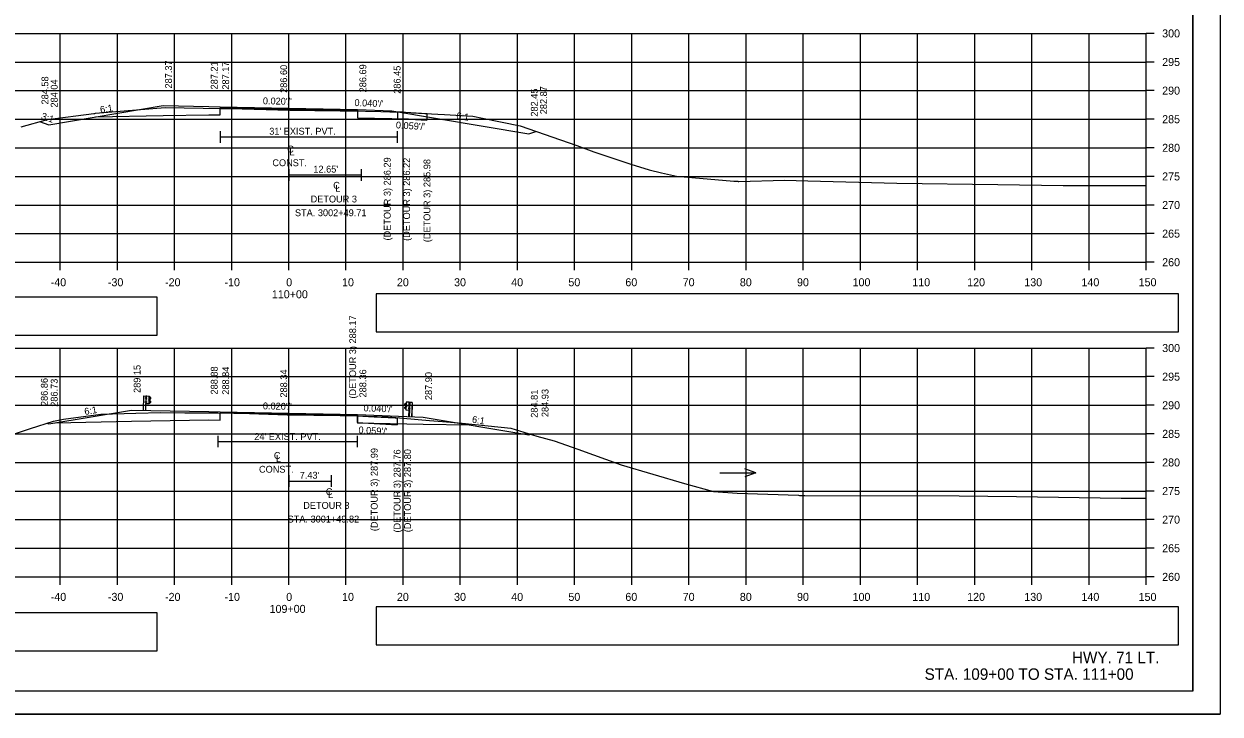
# Model space of a CAD drawing. Extents: x 285 to 4233, y -659 to 3710.
# Drawn here: x 492.9 to 702.2, y 189.5 to 310.1 of the extents above; entities that cross this region are included whole.
import ezdxf

# ---------------------------------------------------------------- set-up
doc = ezdxf.new("R2010")
doc.units = 0
for name, color, linetype in [('R_Alt Surface', 7, 'Continuous'), ('R_Axis', 7, 'Continuous'), ('R_Axis Annot', 7, 'Continuous'), ('R_Border', 7, 'Continuous'), ('R_Detour', 7, 'Continuous'), ('R_Draft', 7, 'Continuous'), ('R_Exist Surface', 7, 'Continuous'), ('R_Fin Surface', 7, 'Continuous'), ('R_Grid', 7, 'Continuous'), ('R_No Plot', 7, 'Continuous'), ('R_Proposed Road', 7, 'Continuous'), ('R_Water', 7, 'Continuous'), ('R_Water Annot', 7, 'Continuous'), ('R_Xsect Elev', 7, 'Continuous'), ('R_Xsect Slope', 7, 'Continuous')]:
    doc.layers.add(name, color=color, linetype=linetype)

# ---------------------------------------------------------------- blocks, each defined once
blk = doc.blocks.new('GUARDRAIL RT_P')
at = {"layer": 'R_Proposed Road'}
for p, q in [((-1.3, 2.2), (-1.17, 2.3)), ((-1.28, 2.18), (-1.16, 2.29)), ((-1.17, 2.3), (-1.06, 2.36)), ((-1.16, 2.29), (-1.06, 2.34)), ((-1.02, 1.15), (-1.02, 2.51)), ((-0.53, 2.21), (-0.58, 2.21)), ((-0.58, 2.21), (-0.58, 2.08)), ((-0.58, 2.15), (-0.52, 2.15)), ((-0.53, 2.52), (-0.52, 2.52)), ((-0.53, 2.52), (-0.46, 2.51)), ((-0.49, 0), (-0.49, 2.52)), ((-0.46, 2.09), (-0.46, 2.21)), ((-0.46, 2.21), (-0.41, 2.21)), ((-0.46, 2.18), (-0.41, 2.18)), ((-0.46, 2.12), (-0.41, 2.12)), ((-0.46, 2.12), (-0.41, 2.12)), ((-0.4, 2.11), (-0.4, 2.2)), ((-0.03, 2.52), (-0.03, 0)), ((0, 2.52), (0, 0)), ((-1.17, 1.35), (-1.3, 1.46)), ((-1.12, 1.95), (-1.29, 2.05)), ((-1.16, 1.37), (-1.29, 1.48)), ((-1.11, 1.97), (-1.28, 2.07)), ((-1.27, 1.62), (-1.12, 1.71)), ((-1.26, 1.6), (-1.1, 1.69)), ((-1.06, 1.29), (-1.17, 1.35)), ((-1.05, 1.31), (-1.16, 1.37)), ((-1.09, 1.77), (-1.09, 1.9)), ((-1.06, 1.77), (-1.06, 1.9)), ((-1.01, 1.77), (-1.01, 1.89)), ((-1.01, 1.89), (-0.96, 1.89)), ((-1.01, 1.86), (-0.96, 1.86)), ((-1.01, 1.8), (-0.97, 1.8)), ((-1.01, 1.8), (-0.96, 1.8)), ((-1.01, 1.77), (-0.96, 1.77)), ((-0.96, 1.78), (-0.96, 1.88)), ((-0.53, 2.08), (-0.58, 2.08)), ((-0.58, 1.4), (-0.58, 1.53)), ((-0.58, 1.53), (-0.53, 1.53)), ((-0.58, 1.46), (-0.52, 1.46)), ((-0.58, 1.4), (-0.53, 1.4)), ((-0.52, 1.15), (-0.49, 1.15)), ((-0.46, 2.09), (-0.41, 2.09)), ((-0.45, 1.4), (-0.45, 1.53)), ((-0.45, 1.53), (-0.4, 1.53)), ((-0.45, 1.49), (-0.4, 1.49)), ((-0.45, 1.43), (-0.4, 1.43)), ((-0.45, 1.43), (-0.4, 1.43)), ((-0.45, 1.4), (-0.4, 1.4)), ((-0.39, 1.42), (-0.39, 1.51))]:
    blk.add_line(p, q, dxfattribs=at)
for points in [[(-1.05, 2.52), (-1.05, 1.15), (-0.52, 1.15), (-0.53, 2.52)], [(-0.58, 2.21), (-0.58, 2.08), (-0.53, 2.08), (-0.53, 2.21)], [(-0.45, 2.23), (-0.45, 2.07), (-0.46, 2.07), (-0.46, 2.23)], [(-0.4, 2.18), (-0.4, 2.12), (-0.37, 2.12), (-0.37, 2.18)], [(-1.01, 1.91), (-1.01, 1.75), (-1.02, 1.75), (-1.02, 1.91)], [(-0.95, 1.86), (-0.95, 1.8), (-0.93, 1.8), (-0.93, 1.86)], [(-0.58, 1.53), (-0.58, 1.4), (-0.53, 1.4), (-0.53, 1.53)], [(-0.44, 1.55), (-0.44, 1.38), (-0.45, 1.38), (-0.45, 1.55)], [(-0.39, 1.49), (-0.39, 1.43), (-0.36, 1.43), (-0.36, 1.49)]]:
    blk.add_lwpolyline(points, close=True, dxfattribs=at)
blk.add_lwpolyline([(0, 2.52), (-0.46, 2.51), (-0.45, 0)], dxfattribs=at)
for centre, radius, start, end in [((-1.25, 2.13), 0.0856, 122.0217, 240.7501), ((-1.25, 2.13), 0.062, 122.0217, 240.7501), ((-0.42, 2.2), 0.022, 317.7756, 45.4255), ((-0.49, 2.15), 0.0922, 339.7423, 20.2577), ((-0.43, 2.1), 0.025, 323.3766, 39.0666), ((-1.22, 1.52), 0.109, 120.88, 214.7816), ((-1.22, 1.52), 0.0854, 120.88, 214.7816), ((-1.08, 1.83), 0.0453, 93.9303, 257.0446), ((-1.15, 1.89), 0.0622, 4.9556, 61.894), ((-1.15, 1.89), 0.0865, 4.9556, 61.894), ((-1.13, 1.76), 0.0462, 293.1464, 8.2196), ((-1.13, 1.76), 0.0703, 293.1464, 8.2196), ((-0.98, 1.88), 0.022, 317.7756, 45.4255), ((-1.05, 1.83), 0.0922, 339.7423, 20.2577), ((-0.98, 1.78), 0.025, 323.3766, 39.0666), ((-0.41, 1.51), 0.022, 317.7756, 45.4255), ((-0.48, 1.46), 0.0922, 339.7423, 20.2577), ((-0.41, 1.41), 0.025, 323.3766, 39.0666)]:
    blk.add_arc(centre, radius, start, end, dxfattribs=at)
blk = doc.blocks.new('GUARDRAIL LT_P')
at = {"layer": 'R_Proposed Road'}
for p, q in [((0, 2.52), (0, 0)), ((0.03, 2.52), (0.03, 0)), ((0.4, 2.11), (0.4, 2.2)), ((0.46, 2.21), (0.41, 2.21)), ((0.46, 2.18), (0.41, 2.18)), ((0.46, 2.12), (0.41, 2.12)), ((0.46, 2.12), (0.41, 2.12)), ((0.53, 2.52), (0.46, 2.51)), ((0.46, 2.09), (0.46, 2.21)), ((0.49, 0), (0.49, 2.52)), ((0.53, 2.52), (0.52, 2.52)), ((0.58, 2.15), (0.52, 2.15)), ((0.53, 2.21), (0.58, 2.21)), ((0.58, 2.21), (0.58, 2.08)), ((1.02, 1.15), (1.02, 2.51)), ((1.17, 2.3), (1.06, 2.36)), ((1.16, 2.29), (1.06, 2.34)), ((1.28, 2.18), (1.16, 2.29)), ((1.3, 2.2), (1.17, 2.3)), ((0.39, 1.42), (0.39, 1.51)), ((0.45, 1.53), (0.4, 1.53)), ((0.45, 1.49), (0.4, 1.49)), ((0.45, 1.43), (0.4, 1.43)), ((0.45, 1.43), (0.4, 1.43)), ((0.45, 1.4), (0.4, 1.4)), ((0.46, 2.09), (0.41, 2.09)), ((0.45, 1.4), (0.45, 1.53)), ((0.52, 1.15), (0.49, 1.15)), ((0.58, 1.46), (0.52, 1.46)), ((0.53, 2.08), (0.58, 2.08)), ((0.58, 1.53), (0.53, 1.53)), ((0.58, 1.4), (0.53, 1.4)), ((0.58, 1.4), (0.58, 1.53)), ((1.01, 1.89), (0.96, 1.89)), ((0.96, 1.78), (0.96, 1.88)), ((1.01, 1.86), (0.96, 1.86)), ((1.01, 1.8), (0.96, 1.8)), ((1.01, 1.77), (0.96, 1.77)), ((1.01, 1.8), (0.97, 1.8)), ((1.01, 1.77), (1.01, 1.89)), ((1.05, 1.31), (1.16, 1.37)), ((1.06, 1.77), (1.06, 1.9)), ((1.06, 1.29), (1.17, 1.35)), ((1.09, 1.77), (1.09, 1.9)), ((1.26, 1.6), (1.1, 1.69)), ((1.11, 1.97), (1.28, 2.07)), ((1.12, 1.95), (1.29, 2.05)), ((1.27, 1.62), (1.12, 1.71)), ((1.16, 1.37), (1.29, 1.48)), ((1.17, 1.35), (1.3, 1.46))]:
    blk.add_line(p, q, dxfattribs=at)
blk.add_lwpolyline([(0, 2.52), (0.46, 2.51), (0.45, 0)], dxfattribs=at)
for points in [[(0.4, 2.18), (0.4, 2.12), (0.37, 2.12), (0.37, 2.18)], [(0.45, 2.23), (0.45, 2.07), (0.46, 2.07), (0.46, 2.23)], [(1.05, 2.52), (1.05, 1.15), (0.52, 1.15), (0.53, 2.52)], [(0.58, 2.21), (0.58, 2.08), (0.53, 2.08), (0.53, 2.21)], [(0.39, 1.49), (0.39, 1.43), (0.36, 1.43), (0.36, 1.49)], [(0.44, 1.55), (0.44, 1.38), (0.45, 1.38), (0.45, 1.55)], [(0.58, 1.53), (0.58, 1.4), (0.53, 1.4), (0.53, 1.53)], [(0.95, 1.86), (0.95, 1.8), (0.93, 1.8), (0.93, 1.86)], [(1.01, 1.91), (1.01, 1.75), (1.02, 1.75), (1.02, 1.91)]]:
    blk.add_lwpolyline(points, close=True, dxfattribs=at)
for centre, radius, start, end in [((0.42, 2.2), 0.022, 134.5745, 222.2244), ((0.49, 2.15), 0.0922, 159.7423, 200.2577), ((0.43, 2.1), 0.025, 140.9334, 216.6234), ((1.25, 2.13), 0.062, 299.2499, 57.9783), ((1.25, 2.13), 0.0856, 299.2499, 57.9783), ((0.41, 1.51), 0.022, 134.5745, 222.2244), ((0.48, 1.46), 0.0922, 159.7423, 200.2577), ((0.41, 1.41), 0.025, 140.9334, 216.6234), ((0.98, 1.88), 0.022, 134.5745, 222.2244), ((1.05, 1.83), 0.0922, 159.7423, 200.2577), ((0.98, 1.78), 0.025, 140.9334, 216.6234), ((1.15, 1.89), 0.0865, 118.106, 175.0444), ((1.13, 1.76), 0.0703, 171.7804, 246.8536), ((1.08, 1.83), 0.0453, 282.9554, 86.0697), ((1.15, 1.89), 0.0622, 118.106, 175.0444), ((1.13, 1.76), 0.0462, 171.7804, 246.8536), ((1.22, 1.52), 0.0854, 325.2184, 59.12), ((1.22, 1.52), 0.109, 325.2184, 59.12)]:
    blk.add_arc(centre, radius, start, end, dxfattribs=at)

msp = doc.modelspace()

# ---------------------------------------------------------------- linework, layer by layer
at = {"layer": 'R_Alt Surface'}
for points in [[(505.44, 293.89), (517.28, 294.12), (525.28, 294.28), (527.28, 294.24), (527.28, 295.49), (551.28, 295.01), (551.28, 293.76), (551.28, 293.76), (557.28, 293.64), (566.12, 293.47)], [(527.24, 291.39), (527.24, 289.39)], [(558.24, 291.39), (558.24, 289.39)], [(527.2, 290.39), (558.24, 290.39)], [(539.28, 284.74), (539.28, 282.74)], [(551.93, 284.74), (551.93, 282.74)], [(539.28, 283.74), (551.93, 283.74)], [(498.44, 240.41), (511.78, 240.68), (525.28, 240.95), (527.28, 240.91), (527.28, 242.16), (551.28, 241.68), (551.28, 240.43), (551.28, 240.43), (562.78, 240.2), (570.87, 240.04)], [(526.86, 238.15), (526.86, 236.15)], [(526.86, 237.15), (551.22, 237.15)], [(551.22, 238.15), (551.22, 236.15)], [(539.28, 231.24), (539.28, 229.24)], [(539.28, 230.24), (546.71, 230.24)], [(546.71, 231.24), (546.71, 229.24)]]:
    msp.add_lwpolyline(points, dxfattribs=at)
at = {"layer": 'R_Axis'}
for p, q in [((689.28, 268.49), (689.28, 308.49)), ((690.68, 308.49), (689.28, 308.49)), ((690.68, 303.49), (689.28, 303.49)), ((690.68, 298.49), (689.28, 298.49)), ((690.68, 293.49), (689.28, 293.49)), ((690.68, 288.49), (689.28, 288.49)), ((690.68, 283.49), (689.28, 283.49)), ((690.68, 278.49), (689.28, 278.49)), ((690.68, 273.49), (689.28, 273.49)), ((389.28, 268.49), (689.28, 268.49)), ((499.28, 267.09), (499.28, 268.49)), ((509.28, 267.09), (509.28, 268.49)), ((519.28, 267.09), (519.28, 268.49)), ((529.28, 267.09), (529.28, 268.49)), ((539.28, 267.09), (539.28, 268.49)), ((549.28, 267.09), (549.28, 268.49)), ((559.28, 267.09), (559.28, 268.49)), ((569.28, 267.09), (569.28, 268.49)), ((579.28, 267.09), (579.28, 268.49)), ((589.28, 267.09), (589.28, 268.49)), ((599.28, 267.09), (599.28, 268.49)), ((609.28, 267.09), (609.28, 268.49)), ((619.28, 267.09), (619.28, 268.49)), ((629.28, 267.09), (629.28, 268.49)), ((639.28, 267.09), (639.28, 268.49)), ((649.28, 267.09), (649.28, 268.49)), ((659.28, 267.09), (659.28, 268.49)), ((669.28, 267.09), (669.28, 268.49)), ((679.28, 267.09), (679.28, 268.49)), ((689.28, 267.09), (689.28, 268.49)), ((690.68, 268.49), (689.28, 268.49)), ((689.28, 213.49), (689.28, 253.49)), ((690.68, 253.49), (689.28, 253.49)), ((690.68, 248.49), (689.28, 248.49)), ((690.68, 243.49), (689.28, 243.49)), ((690.68, 238.49), (689.28, 238.49)), ((690.68, 233.49), (689.28, 233.49)), ((690.68, 228.49), (689.28, 228.49)), ((690.68, 223.49), (689.28, 223.49)), ((690.68, 218.49), (689.28, 218.49)), ((389.28, 213.49), (689.28, 213.49)), ((499.28, 212.09), (499.28, 213.49)), ((509.28, 212.09), (509.28, 213.49)), ((519.28, 212.09), (519.28, 213.49)), ((529.28, 212.09), (529.28, 213.49)), ((539.28, 212.09), (539.28, 213.49)), ((549.28, 212.09), (549.28, 213.49)), ((559.28, 212.09), (559.28, 213.49)), ((569.28, 212.09), (569.28, 213.49)), ((579.28, 212.09), (579.28, 213.49)), ((589.28, 212.09), (589.28, 213.49)), ((599.28, 212.09), (599.28, 213.49)), ((609.28, 212.09), (609.28, 213.49)), ((619.28, 212.09), (619.28, 213.49)), ((629.28, 212.09), (629.28, 213.49)), ((639.28, 212.09), (639.28, 213.49)), ((649.28, 212.09), (649.28, 213.49)), ((659.28, 212.09), (659.28, 213.49)), ((669.28, 212.09), (669.28, 213.49)), ((679.28, 212.09), (679.28, 213.49)), ((689.28, 212.09), (689.28, 213.49)), ((690.68, 213.49), (689.28, 213.49))]:
    msp.add_line(p, q, dxfattribs=at)
at = {"layer": 'R_Axis Annot'}
for points in [[(388.91, 255.75), (516.24, 255.75), (516.24, 262.41), (388.91, 262.41)], [(554.55, 256.3), (694.92, 256.3), (694.92, 262.96), (554.55, 262.96)], [(388.91, 200.57), (516.24, 200.57), (516.24, 207.23), (388.91, 207.23)], [(554.55, 201.58), (694.92, 201.58), (694.92, 208.23), (554.55, 208.23)]]:
    msp.add_lwpolyline(points, close=True, dxfattribs=at)
at = {"layer": 'R_Border'}
for q in [(697.46, 398.95), (381.28, 193.49)]:
    msp.add_line((697.46, 193.49), q, dxfattribs=at)
at = {"layer": 'R_Detour'}
for p, q in [((558.32, 294.78), (558.32, 293.61)), ((563.45, 294.47), (563.45, 293.31)), ((551.22, 241.66), (551.21, 240.49)), ((558.22, 241.25), (558.22, 240.08))]:
    msp.add_line(p, q, dxfattribs=at)
for points in [[(558.32, 294.78), (558.36, 294.78), (559.44, 294.71), (559.67, 294.7), (563.45, 294.47), (563.46, 294.48), (563.47, 294.47)], [(558.32, 293.61), (558.32, 293.61), (559.44, 293.54), (563.45, 293.31)], [(551.22, 241.66), (554.22, 241.48), (557.91, 241.27), (558.22, 241.25), (558.23, 241.25), (558.36, 241.3)], [(551.22, 240.49), (551.22, 240.49), (554.22, 240.32), (558.22, 240.08)]]:
    msp.add_lwpolyline(points, dxfattribs=at)
at = {"layer": 'R_Exist Surface'}
for points in [[(492.44, 292.14), (497.03, 293.46), (505.17, 294.49), (505.27, 294.5), (505.32, 294.51), (505.46, 294.52), (517.66, 295.51), (524.27, 295.42), (527.24, 295.39), (531.09, 295.29), (539.43, 295.09), (543.81, 295.02), (552.71, 294.87), (555.35, 294.83), (556.95, 294.81), (557.65, 294.8), (558.32, 294.78), (559.24, 294.76), (559.71, 294.72), (560.47, 294.65), (560.78, 294.62), (566.5, 294.31), (571.45, 294.03), (573.18, 293.68), (579.75, 292.32), (589.65, 288.87), (592.65, 287.78), (599.14, 285.66), (602.3, 284.65), (604.47, 284.11), (607.11, 283.55), (617.15, 282.69), (617.81, 282.64), (617.87, 282.63), (617.89, 282.63), (617.93, 282.63), (618.02, 282.63), (626.03, 282.82), (630.08, 282.7), (645.68, 282.33), (663.31, 282.06), (674.76, 281.88), (689.23, 281.88), (689.28, 281.88)], [(486.6, 236.96), (494.1, 239.43), (498.08, 240.73), (499.83, 241.03), (506.38, 241.95), (512.5, 242.1), (516.88, 242.23), (521.09, 242.19), (526.86, 242.15), (532.38, 242.02), (539.01, 241.84), (548.27, 241.7), (551.22, 241.66), (552.83, 241.6), (556.67, 241.44), (563.89, 240.82), (566.17, 240.63), (569.63, 240.33), (578.13, 239.5), (582.65, 238.11), (585.7, 237.27), (589.84, 235.81), (597.42, 233.09), (608.51, 229.82), (613.6, 228.42), (615.24, 228.27), (616.11, 228.23), (617.74, 228.15), (628.46, 227.75), (628.63, 227.74), (629.56, 227.74), (656.54, 227.66), (666.57, 227.53), (684.88, 227.26), (689.28, 227.22)]]:
    msp.add_lwpolyline(points, dxfattribs=at)
at = {"layer": 'R_Fin Surface'}
for points in [[(495.66, 293.07), (497.28, 292.53), (517.28, 295.86), (525.28, 295.7), (527.28, 295.66), (551.28, 295.18), (557.28, 294.94), (581.28, 290.94), (582.52, 291.36)], [(496.9, 240.35), (497.28, 240.22), (511.78, 242.64), (525.28, 242.37), (527.28, 242.33), (551.28, 241.85), (562.78, 241.39), (581.28, 238.3), (581.63, 238.42)]]:
    msp.add_lwpolyline(points, dxfattribs=at)
at = {"layer": 'R_Grid'}
for p, q in [((389.28, 308.49), (689.28, 308.49)), ((499.28, 268.49), (499.28, 308.49)), ((509.28, 268.49), (509.28, 308.49)), ((519.28, 268.49), (519.28, 308.49)), ((529.28, 268.49), (529.28, 308.49)), ((539.28, 268.49), (539.28, 308.49)), ((549.28, 268.49), (549.28, 308.49)), ((559.28, 268.49), (559.28, 308.49)), ((569.28, 268.49), (569.28, 308.49)), ((579.28, 268.49), (579.28, 308.49)), ((589.28, 268.49), (589.28, 308.49)), ((599.28, 268.49), (599.28, 308.49)), ((609.28, 268.49), (609.28, 308.49)), ((619.28, 268.49), (619.28, 308.49)), ((629.28, 268.49), (629.28, 308.49)), ((639.28, 268.49), (639.28, 308.49)), ((649.28, 268.49), (649.28, 308.49)), ((659.28, 268.49), (659.28, 308.49)), ((669.28, 268.49), (669.28, 308.49)), ((679.28, 268.49), (679.28, 308.49)), ((689.28, 268.49), (689.28, 308.49)), ((389.28, 303.49), (689.28, 303.49)), ((389.28, 298.49), (689.28, 298.49)), ((389.28, 293.49), (689.28, 293.49)), ((389.28, 288.49), (689.28, 288.49)), ((389.28, 283.49), (689.28, 283.49)), ((389.28, 278.49), (689.28, 278.49)), ((389.28, 273.49), (689.28, 273.49)), ((389.28, 268.49), (689.28, 268.49)), ((389.28, 253.49), (689.28, 253.49)), ((499.28, 213.49), (499.28, 253.49)), ((509.28, 213.49), (509.28, 253.49)), ((519.28, 213.49), (519.28, 253.49)), ((529.28, 213.49), (529.28, 253.49)), ((539.28, 213.49), (539.28, 253.49)), ((549.28, 213.49), (549.28, 253.49)), ((559.28, 213.49), (559.28, 253.49)), ((569.28, 213.49), (569.28, 253.49)), ((579.28, 213.49), (579.28, 253.49)), ((589.28, 213.49), (589.28, 253.49)), ((599.28, 213.49), (599.28, 253.49)), ((609.28, 213.49), (609.28, 253.49)), ((619.28, 213.49), (619.28, 253.49)), ((629.28, 213.49), (629.28, 253.49)), ((639.28, 213.49), (639.28, 253.49)), ((649.28, 213.49), (649.28, 253.49)), ((659.28, 213.49), (659.28, 253.49)), ((669.28, 213.49), (669.28, 253.49)), ((679.28, 213.49), (679.28, 253.49)), ((689.28, 213.49), (689.28, 253.49)), ((389.28, 248.49), (689.28, 248.49)), ((389.28, 243.49), (689.28, 243.49)), ((389.28, 238.49), (689.28, 238.49)), ((389.28, 233.49), (689.28, 233.49)), ((389.28, 228.49), (689.28, 228.49)), ((389.28, 223.49), (689.28, 223.49)), ((389.28, 218.49), (689.28, 218.49)), ((389.28, 213.49), (689.28, 213.49))]:
    msp.add_line(p, q, dxfattribs=at)
at = {"layer": 'R_No Plot'}
msp.add_line((368.88, 189.51), (702.21, 189.51), dxfattribs=at)
for points in [[(368.87, 402.85), (702.21, 402.85), (702.21, 189.51), (368.87, 189.51)], [(615.2, 398.95), (634.82, 398.95), (634.82, 389.07), (650.93, 389.07), (674.13, 389.07), (674.25, 360.91), (697.46, 360.91), (697.46, 193.49), (381.28, 193.49), (381.28, 398.95)]]:
    msp.add_lwpolyline(points, close=True, dxfattribs=at)
at = {"layer": 'R_Water Annot'}
for p, q in [((621, 231.67), (619.07, 232.37)), ((614.71, 231.67), (621, 231.67)), ((621, 231.67), (619.07, 230.97))]:
    msp.add_line(p, q, dxfattribs=at)
at = {"layer": 'R_Xsect Elev'}
for p, q in [((539.28, 295.09), (539.28, 305.09)), ((539.28, 241.83), (539.28, 251.83))]:
    msp.add_line(p, q, dxfattribs=at)

# ---------------------------------------------------------------- block references
at = {"layer": 'R_Water'}
for name, p, rotation in [('GUARDRAIL LT_P', (513.78, 242.6), -1.1141888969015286), ('GUARDRAIL RT_P', (560.78, 241.47), -2.3041645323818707)]:
    msp.add_blockref(name, p, dxfattribs=dict(at, rotation=rotation))

# ---------------------------------------------------------------- texts
at = {"layer": 'R_Alt Surface'}
for s, height, p in [('C', 1.2, (539, 287.67)), ('L', 1.2, (539.38, 287.15)), ('CONST.', 1.199, (536.4, 285.28)), ('C', 1.2, (547.04, 281.34)), ('L', 1.2, (547.42, 280.81)), ('DETOUR 3', 1.199, (543.09, 278.94)), ('STA. 3002+49.71', 1.1985, (540.35, 276.54)), ('C', 1.2, (536.66, 234.1)), ('L', 1.2, (537.04, 233.57)), ('CONST.', 1.199, (534.06, 231.7)), ('C', 1.2, (545.75, 227.78)), ('L', 1.2, (546.14, 227.25)), ('DETOUR 3', 1.199, (541.8, 225.38)), ('STA. 3001+49.82', 1.1985, (539.07, 222.99))]:
    msp.add_text(s, height=height, dxfattribs=at).set_placement(p)
at = {"layer": 'R_Axis Annot'}
for s, p in [('300', (692.08, 307.79)), ('295', (692.08, 302.79)), ('290', (692.08, 297.79)), ('285', (692.08, 292.79)), ('280', (692.08, 287.79)), ('275', (692.08, 282.79)), ('270', (692.08, 277.79)), ('265', (692.08, 272.79)), ('260', (692.08, 267.79)), ('-40', (497.62, 264.29)), ('-30', (507.62, 264.29)), ('-20', (517.62, 264.29)), ('-10', (528.02, 264.29)), ('0', (538.82, 264.29)), ('10', (548.59, 264.29)), ('20', (558.19, 264.29)), ('30', (568.19, 264.29)), ('40', (578.19, 264.29)), ('50', (588.19, 264.29)), ('60', (598.16, 264.29)), ('70', (608.19, 264.29)), ('80', (618.19, 264.29)), ('90', (628.19, 264.29)), ('100', (637.91, 264.29)), ('110', (648.36, 264.29)), ('120', (657.96, 264.29)), ('130', (667.96, 264.29)), ('140', (677.96, 264.29)), ('150', (687.96, 264.29)), ('110+00', (536.31, 262.19)), ('300', (692.08, 252.79)), ('295', (692.08, 247.79)), ('290', (692.08, 242.79)), ('285', (692.08, 237.79)), ('280', (692.08, 232.79)), ('275', (692.08, 227.79)), ('270', (692.08, 222.79)), ('265', (692.08, 217.79)), ('260', (692.08, 212.79)), ('-40', (497.62, 209.29)), ('-30', (507.62, 209.29)), ('-20', (517.62, 209.29)), ('-10', (528.02, 209.29)), ('0', (538.82, 209.29)), ('10', (548.59, 209.29)), ('20', (558.19, 209.29)), ('30', (568.19, 209.29)), ('40', (578.19, 209.29)), ('50', (588.19, 209.29)), ('60', (598.16, 209.29)), ('70', (608.19, 209.29)), ('80', (618.19, 209.29)), ('90', (628.19, 209.29)), ('100', (637.91, 209.29)), ('110', (648.36, 209.29)), ('120', (657.96, 209.29)), ('130', (667.96, 209.29)), ('140', (677.96, 209.29)), ('150', (687.96, 209.29)), ('109+00', (535.91, 207.19))]:
    msp.add_text(s, height=1.4, dxfattribs=at).set_placement(p)
at = {"layer": 'R_Draft'}
for s, p in [('HWY. 71 LT.', (676.29, 198.4)), ('STA. 109+00 TO STA. 111+00', (650.51, 195.49))]:
    msp.add_text(s, height=2, dxfattribs=at).set_placement(p)
at = {"layer": 'R_Water'}
for s, p in [("31' EXIST. PVT.", (535.85, 290.79)), ("12.65'", (543.57, 284.16)), ("24' EXIST. PVT.", (533.23, 237.42)), ("7.43'", (541.18, 230.65))]:
    msp.add_text(s, height=1.2, dxfattribs=at).set_placement(p)
at = {"layer": 'R_Xsect Elev'}
for s, p in [('287.37', (518.83, 298.86)), ('287.21', (526.83, 298.7)), ('287.17', (528.83, 298.66)), ('286.60', (538.98, 298.09)), ('286.69', (552.83, 298.18)), ('286.45', (558.83, 297.94)), ('284.58', (497.21, 296.07)), ('284.04', (498.83, 295.53)), ('282.45', (582.83, 293.94)), ('282.87', (584.44, 294.36)), ('(DETOUR 3) 286.29', (557.1, 272.29)), ('(DETOUR 3) 286.22', (560.49, 272.22)), ('(DETOUR 3) 285.98', (564.05, 271.99)), ('(DETOUR 3) 288.17', (551.05, 244.66)), ('289.15', (513.33, 245.64)), ('288.88', (526.83, 245.37)), ('288.84', (528.83, 245.33)), ('288.34', (538.98, 244.83)), ('288.36', (552.83, 244.85)), ('287.90', (564.33, 244.39)), ('286.86', (497.1, 243.35)), ('286.73', (498.83, 243.22)), ('284.81', (582.83, 241.3)), ('284.93', (584.71, 241.42)), ('(DETOUR 3) 287.99', (554.82, 221.48)), ('(DETOUR 3) 287.76', (558.82, 221.24)), ('(DETOUR 3) 287.80', (560.65, 221.29))]:
    msp.add_text(s, height=1.2, rotation=90, dxfattribs=at).set_placement(p)
at = {"layer": 'R_Xsect Slope'}
for s, rotation, p in [("0.020'/'", 358.8542, (534.73, 296.11)), ('6:1', 9.4623, (506.35, 294.55)), ("0.040'/'", 357.7094, (550.74, 295.8)), ('3:1', 341.5651, (495.84, 293.54)), ("0.059'/'", 356.614, (557.98, 291.9)), ('6:1', 350.5377, (568.51, 293.58)), ('6:1', 9.4623, (503.6, 241.78)), ("0.020'/'", 358.8542, (534.73, 242.78)), ("0.040'/'", 357.7094, (552.33, 242.43)), ('6:1', 350.5377, (571.26, 240.48)), ("0.059'/'", 356.6435, (551.43, 238.6))]:
    msp.add_text(s, height=1.2, rotation=rotation, dxfattribs=at).set_placement(p)

doc.saveas('drawing.dxf')
